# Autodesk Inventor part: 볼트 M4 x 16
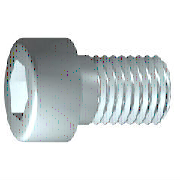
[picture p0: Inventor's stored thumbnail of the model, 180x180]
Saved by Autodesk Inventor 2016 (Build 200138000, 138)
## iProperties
Created: 2012-02
Part Number: 볼트 M4 x 16
Material: 스테인리스강
Description: 6각 소켓 머리 캡 나사
Document SubType Name: Modeling
Standard: ISO 4762
Designer: mduedu
Standard Revision: Fourth edition 2004-03-01
Standards Organization: ISO
Language: ko-KR
Size Designation: M4 x 16
Categories: <MemberInstance><Categories><Category DisplayName="조임쇠" InternalName="e4da775c-781d-43d5-af7c-5136215cf5a6" Mnemonic="FSTN"><Category DisplayName="볼트" InternalN
Density: 7.75 g/cm^3
Appearance: 반광택
IsCustomPart: 0
Author: mduedu
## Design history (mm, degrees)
sketch "스케치1"
  geometry: L1 (-1, 0)-(16, 0); L2 (16, 0)-(16, 2); L3 (16, 2)-(1.75, 2); L4 (1.75, 2)-(1.32, 2); L5 (1.32, 2)-(0, 2); L6 (0, 2)-(0, 3.5); L7 (0, 3.5)-(-4, 3.5); L8 (-4, 3.5)-(-4, 1.732); L9 (-4, 1.732)-(-2, 1.732); L10 (-2, 1.732)-(-1, 0); L11 (-8, 0)-(20, 0) reference; L12 (0, -0.7)-(0, 4.2) reference; L13 (1.75, 2)-(0, 2)
  constraints: 22 end point, 6 parallel, 2 collinear, 2 perpendicular, 1 horizontal, 1 point on line
  dimensions: "d1" = 14.25 distance from line of L3.end L2 (= GEL); "d2" = 0.42952 distance of L4.end L3.end (computed from GAL); "d3" = 4 distance between parallel lines of L8 L6 (= KOH); "d4" = 2 distance of L8.end L9.end (= INTI); "d5" = 60 deg angle of L10 L1; "d6" = 4 diameter of L3 L1 (= GD); "d7" = 4 diameter of L5 L1 (= BDM); "d8" = 3.4641 diameter of L9 L1 (= 1.1547 x SW); "d9" = 7 diameter of L7 L1 (= KOD); "d26" = 16 distance between parallel lines of L12 L2 (= NLG)
revolve "본체" sketch "스케치1" stored, may be unused: angle "d10" = 90 deg
sketch "스케치2"
  geometry: L1 (0, -4.9)-(0, 4.9) reference; L2 (-4.9, 0)-(4.9, 0) reference; L3 (1.732, 0)-(0.866, -1.5); L4 (0.866, -1.5)-(-0.866, -1.5); L5 (-0.866, -1.5)-(-1.732, 0); L6 (-1.732, 0)-(-0.866, 1.5); L7 (-0.866, 1.5)-(0.866, 1.5); L8 (0.866, 1.5)-(1.732, 0); 2 further points
  constraints: 12 end point, 1 coincident, 1 horizontal alignment, 1 point on line, 12 other
extrude "슬롯" join sketch "스케치2" stored distance "d11" = 10; taper "d12" = 0 deg
workplane "Work Plane1"
fillet "Fillet2" dims "d30" = 0.1 (= R)
body "Solid1"
fillet "모깎기1" dims "d17" = 0.4 (= RR)
feature "스레드" dims "d13" = 14.25 (= GEL), "d14" = 0
chamfer "모따기1" distance "d15" = 0.42941 (= -0.5 x SPD + 0.5 x GD); stored, may be unused: second distance "d16" = 0.42941 (= GUL), angle "d27" = 45 deg
other parameters: "GD" = 4 [user parameter; used in 2 equation terms], "NLG" = 16 [user parameter; used in 1 equation term], "GEL" = 14.25 [user parameter; used in 2 equation terms], "KOD" = 7 [user parameter; used in 1 equation term], "KOH" = 4 [user parameter; used in 1 equation term], "INTI" = 2 [user parameter; used in 1 equation term], "GAL" = 0.42941 (= 0.61345 x PTC) [user parameter; used in 1 equation term], "GUL" = 0.42941 (= 0.61345 x PTC) [user parameter; used in 1 equation term], "BDM" = 4 (= NND) [user parameter; used in 1 equation term], "SW" = 3 [user parameter; used in 2 equation terms], "RR" = 0.4 [user parameter; used in 1 equation term], "SPD" = 3.14117 (= NND - 1.2269 x PTC) [user parameter; used in 1 equation term], "d19" = 0, "d28" = 0, "d29" = 0, "R" = 0.1 [user parameter; used in 1 equation term], "TOA" = 30 deg [user parameter], "GD1" = 3.14117 (= THREADDIA - 1.2269 x PTC) [user parameter], "THREADDIA" = 4 [user parameter; used in 1 equation term], "FAWI" = 45 deg [user parameter], "TPU" = 14.28571 (computed from PTC) [user parameter], "PTC" = 0.7 [user parameter; used in 5 equation terms], "NND" = 4 [user parameter; used in 2 equation terms], "E0" = 3.465 (= 1.155 x SW) [user parameter]
